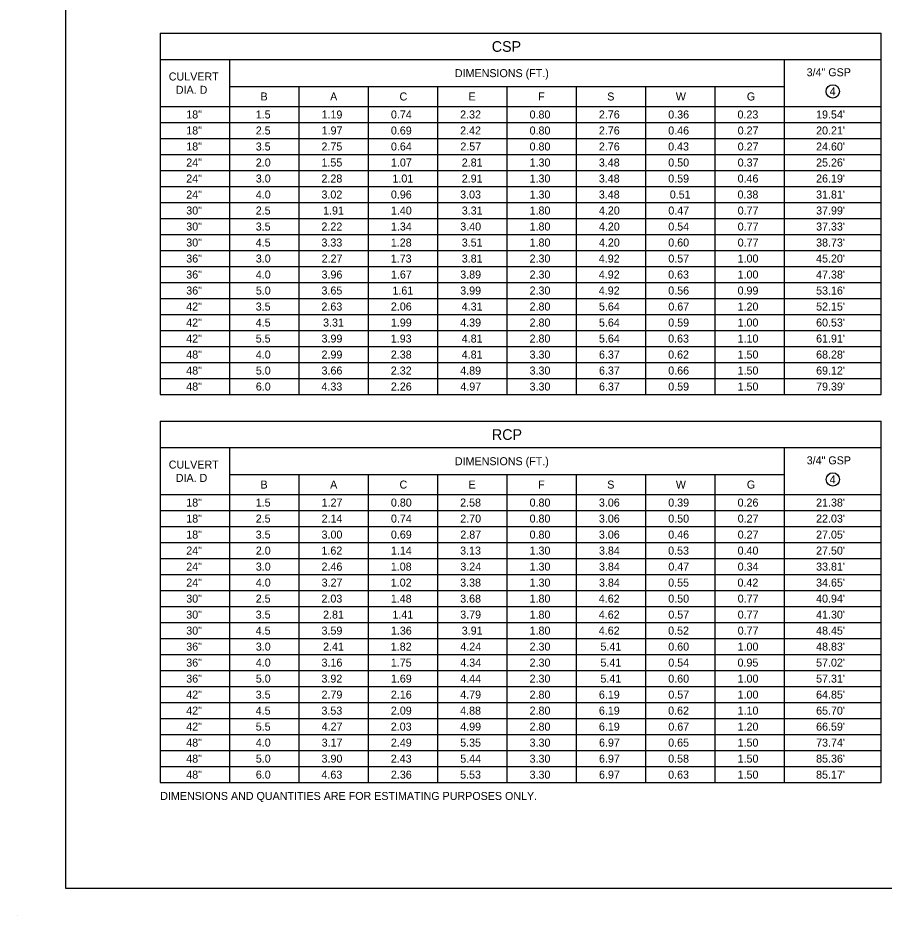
# Model space of a CAD drawing. Extents: x 49991.4 to 50021, y 49987.6 to 50011.4.
# Drawn here: x 49999.02 to 50005.52, y 49987.6 to 49994.33 of the extents above; entities that cross this region are included whole.
import ezdxf

# ---------------------------------------------------------------- set-up
doc = ezdxf.new("R2010")
doc.units = 0
for name, color, linetype in [('Level 1', 7, 'Continuous'), ('Level 2', 7, 'Continuous'), ('Level 3', 7, 'Continuous')]:
    doc.layers.add(name, color=color, linetype=linetype)

msp = doc.modelspace()

# ---------------------------------------------------------------- linework, layer by layer
at = {"layer": 'Level 1'}
msp.add_line((49999.0245, 49987.5988), (49999.0245, 49987.5988), dxfattribs=at)
msp.add_lwpolyline([(49999.3835, 49998.9992), (50016.7501, 49998.9992), (50016.7501, 49987.7988), (49999.3835, 49987.7988)], close=True, dxfattribs=at)
at = {"layer": 'Level 2'}
for p, q in [((50000.0916, 49994.2119), (50005.4993, 49994.2119)), ((50000.0916, 49994.2119), (50000.0916, 49991.5019)), ((50005.4993, 49991.5019), (50005.4993, 49994.2119)), ((50005.4993, 49994.0119), (50000.0916, 49994.0119)), ((50000.6116, 49994.0119), (50000.6116, 49991.5019)), ((50004.7716, 49994.0119), (50004.7716, 49991.5019)), ((50000.6116, 49993.8119), (50004.7716, 49993.8119)), ((50001.1316, 49993.8119), (50001.1316, 49991.5019)), ((50001.6516, 49993.8119), (50001.6516, 49991.5019)), ((50002.1716, 49993.8119), (50002.1716, 49991.5019)), ((50002.6916, 49993.8119), (50002.6916, 49991.5019)), ((50003.2116, 49993.8119), (50003.2116, 49991.5019)), ((50003.7316, 49993.8119), (50003.7316, 49991.5019)), ((50004.2516, 49993.8119), (50004.2516, 49991.5019)), ((50000.0916, 49993.6619), (50005.4993, 49993.6619)), ((50000.0916, 49993.5419), (50005.4993, 49993.5419)), ((50000.0916, 49993.4219), (50005.4993, 49993.4219)), ((50000.0916, 49993.3019), (50005.4993, 49993.3019)), ((50000.0916, 49993.1819), (50005.4993, 49993.1819)), ((50000.0916, 49993.0619), (50005.4993, 49993.0619)), ((50000.0916, 49992.9419), (50005.4993, 49992.9419)), ((50000.0916, 49992.8219), (50005.4993, 49992.8219)), ((50000.0916, 49992.7019), (50005.4993, 49992.7019)), ((50000.0916, 49992.5819), (50005.4993, 49992.5819)), ((50000.0916, 49992.4619), (50005.4993, 49992.4619)), ((50000.0916, 49992.3419), (50005.4993, 49992.3419)), ((50000.0916, 49992.2219), (50005.4993, 49992.2219)), ((50000.0916, 49992.1019), (50005.4993, 49992.1019)), ((50000.0916, 49991.9819), (50005.4993, 49991.9819)), ((50000.0916, 49991.8619), (50005.4993, 49991.8619)), ((50000.0916, 49991.7419), (50005.4993, 49991.7419)), ((50000.0916, 49991.6219), (50005.4993, 49991.6219)), ((50000.0916, 49991.5019), (50005.4993, 49991.5019)), ((50000.0916, 49991.3019), (50005.4993, 49991.3019)), ((50000.0916, 49991.3019), (50000.0916, 49988.5919)), ((50005.4993, 49988.5919), (50005.4993, 49991.3019)), ((50005.4993, 49991.1019), (50000.0916, 49991.1019)), ((50000.6116, 49991.1019), (50000.6116, 49988.5919)), ((50004.7716, 49991.1019), (50004.7716, 49988.5919)), ((50000.6116, 49990.9019), (50004.7716, 49990.9019)), ((50001.1316, 49990.9019), (50001.1316, 49988.5919)), ((50001.6516, 49990.9019), (50001.6516, 49988.5919)), ((50002.1716, 49990.9019), (50002.1716, 49988.5919)), ((50002.6916, 49990.9019), (50002.6916, 49988.5919)), ((50003.2116, 49990.9019), (50003.2116, 49988.5919)), ((50003.7316, 49990.9019), (50003.7316, 49988.5919)), ((50004.2516, 49990.9019), (50004.2516, 49988.5919)), ((50000.0916, 49990.7519), (50005.4993, 49990.7519)), ((50000.0916, 49990.6319), (50005.4993, 49990.6319)), ((50000.0916, 49990.5119), (50005.4993, 49990.5119)), ((50000.0916, 49990.3919), (50005.4993, 49990.3919)), ((50000.0916, 49990.2719), (50005.4993, 49990.2719)), ((50000.0916, 49990.1519), (50005.4993, 49990.1519)), ((50000.0916, 49990.0319), (50005.4993, 49990.0319)), ((50000.0916, 49989.9119), (50005.4993, 49989.9119)), ((50000.0916, 49989.7919), (50005.4993, 49989.7919)), ((50000.0916, 49989.6719), (50005.4993, 49989.6719)), ((50000.0916, 49989.5519), (50005.4993, 49989.5519)), ((50000.0916, 49989.4319), (50005.4993, 49989.4319)), ((50000.0916, 49989.3119), (50005.4993, 49989.3119)), ((50000.0916, 49989.1919), (50005.4993, 49989.1919)), ((50000.0916, 49989.0719), (50005.4993, 49989.0719)), ((50000.0916, 49988.9519), (50005.4993, 49988.9519)), ((50000.0916, 49988.8319), (50005.4993, 49988.8319)), ((50000.0916, 49988.7119), (50005.4993, 49988.7119)), ((50000.0916, 49988.5919), (50005.4993, 49988.5919))]:
    msp.add_line(p, q, dxfattribs=at)
at = {"layer": 'Level 3'}
for centre in [(50005.1354, 49993.7752), (50005.1355, 49990.8652)]:
    msp.add_circle(centre, 0.05, dxfattribs=at)

# ---------------------------------------------------------------- texts
at = {"layer": 'Level 2'}
for s, height, p in [('CSP', 0.08, (50002.5778, 49994.0718)), ('CULVERT', 0.06, (50000.1558, 49993.8569)), ('DIMENSIONS (FT.)', 0.06, (50002.3014, 49993.8819)), ('3/4" GSP', 0.06, (50004.9392, 49993.8885)), ('DIA. D', 0.06, (50000.2087, 49993.7569)), ('B', 0.06, (50000.8439, 49993.7069)), ('A', 0.06, (50001.3658, 49993.7069)), ('C', 0.06, (50001.8861, 49993.7069)), ('E', 0.06, (50002.4036, 49993.7069)), ('F', 0.06, (50002.9254, 49993.7069)), ('S', 0.06, (50003.4438, 49993.7069)), ('W', 0.06, (50003.9583, 49993.7069)), ('G', 0.06, (50004.4909, 49993.7069)), ('4', 0.06, (50005.1115, 49993.7452)), ('18"', 0.06, (50000.2867, 49993.5719)), ('1.5', 0.06, (50000.8079, 49993.5719)), ('1.19', 0.06, (50001.3014, 49993.5719)), ('0.74', 0.06, (50001.8219, 49993.5719)), ('2.32', 0.06, (50002.3407, 49993.5719)), ('0.80', 0.06, (50002.8615, 49993.5719)), ('2.76', 0.06, (50003.3814, 49993.5719)), ('0.36', 0.06, (50003.9014, 49993.5719)), ('0.23', 0.06, (50004.4207, 49993.5719)), ("19.54'", 0.06, (50005.0102, 49993.5719)), ('18"', 0.06, (50000.2867, 49993.4519)), ('2.5', 0.06, (50000.8079, 49993.4519)), ('1.97', 0.06, (50001.3021, 49993.4519)), ('0.69', 0.06, (50001.8214, 49993.4519)), ('2.42', 0.06, (50002.3407, 49993.4519)), ('0.80', 0.06, (50002.8615, 49993.4519)), ('2.76', 0.06, (50003.3814, 49993.4519)), ('0.46', 0.06, (50003.9014, 49993.4519)), ('0.27', 0.06, (50004.4221, 49993.4519)), ("20.21'", 0.06, (50005.0102, 49993.4519)), ('18"', 0.06, (50000.2867, 49993.3319)), ('3.5', 0.06, (50000.8079, 49993.3319)), ('2.75', 0.06, (50001.301, 49993.3319)), ('0.64', 0.06, (50001.8219, 49993.3319)), ('2.57', 0.06, (50002.3421, 49993.3319)), ('0.80', 0.06, (50002.8615, 49993.3319)), ('2.76', 0.06, (50003.3814, 49993.3319)), ('0.43', 0.06, (50003.9007, 49993.3319)), ('0.27', 0.06, (50004.4221, 49993.3319)), ("24.60'", 0.06, (50005.0102, 49993.3319)), ('24"', 0.06, (50000.2867, 49993.2119)), ('2.0', 0.06, (50000.8085, 49993.2119)), ('1.55', 0.06, (50001.301, 49993.2119)), ('1.07', 0.06, (50001.8221, 49993.2119)), ('2.81', 0.06, (50002.3529, 49993.2119)), ('1.30', 0.06, (50002.8615, 49993.2119)), ('3.48', 0.06, (50003.3809, 49993.2119)), ('0.50', 0.06, (50003.9015, 49993.2119)), ('0.37', 0.06, (50004.4221, 49993.2119)), ("25.26'", 0.06, (50005.0102, 49993.2119)), ('24"', 0.06, (50000.2867, 49993.0919)), ('3.0', 0.06, (50000.8085, 49993.0919)), ('2.28', 0.06, (50001.3009, 49993.0919)), ('1.01', 0.06, (50001.8329, 49993.0919)), ('2.91', 0.06, (50002.3529, 49993.0919)), ('1.30', 0.06, (50002.8615, 49993.0919)), ('3.48', 0.06, (50003.3809, 49993.0919)), ('0.59', 0.06, (50003.9014, 49993.0919)), ('0.46', 0.06, (50004.4214, 49993.0919)), ("26.19'", 0.06, (50005.0102, 49993.0919)), ('24"', 0.06, (50000.2867, 49992.9719)), ('4.0', 0.06, (50000.8085, 49992.9719)), ('3.02', 0.06, (50001.3007, 49992.9719)), ('0.96', 0.06, (50001.8214, 49992.9719)), ('3.03', 0.06, (50002.3407, 49992.9719)), ('1.30', 0.06, (50002.8615, 49992.9719)), ('3.48', 0.06, (50003.3809, 49992.9719)), ('0.51', 0.06, (50003.9129, 49992.9719)), ('0.38', 0.06, (50004.4209, 49992.9719)), ("31.81'", 0.06, (50005.0102, 49992.9719)), ('30"', 0.06, (50000.2867, 49992.8519)), ('2.5', 0.06, (50000.8079, 49992.8519)), ('1.91', 0.06, (50001.3129, 49992.8519)), ('1.40', 0.06, (50001.8215, 49992.8519)), ('3.31', 0.06, (50002.3529, 49992.8519)), ('1.80', 0.06, (50002.8615, 49992.8519)), ('4.20', 0.06, (50003.3815, 49992.8519)), ('0.47', 0.06, (50003.9021, 49992.8519)), ('0.77', 0.06, (50004.4221, 49992.8519)), ("37.99'", 0.06, (50005.0102, 49992.8519)), ('30"', 0.06, (50000.2867, 49992.7319)), ('3.5', 0.06, (50000.8079, 49992.7319)), ('2.22', 0.06, (50001.3007, 49992.7319)), ('1.34', 0.06, (50001.8219, 49992.7319)), ('3.40', 0.06, (50002.3415, 49992.7319)), ('1.80', 0.06, (50002.8615, 49992.7319)), ('4.20', 0.06, (50003.3815, 49992.7319)), ('0.54', 0.06, (50003.9019, 49992.7319)), ('0.77', 0.06, (50004.4221, 49992.7319)), ("37.33'", 0.06, (50005.0102, 49992.7319)), ('30"', 0.06, (50000.2867, 49992.6119)), ('4.5', 0.06, (50000.8079, 49992.6119)), ('3.33', 0.06, (50001.3007, 49992.6119)), ('1.28', 0.06, (50001.8209, 49992.6119)), ('3.51', 0.06, (50002.3529, 49992.6119)), ('1.80', 0.06, (50002.8615, 49992.6119)), ('4.20', 0.06, (50003.3815, 49992.6119)), ('0.60', 0.06, (50003.9015, 49992.6119)), ('0.77', 0.06, (50004.4221, 49992.6119)), ("38.73'", 0.06, (50005.0102, 49992.6119)), ('36"', 0.06, (50000.2867, 49992.4919)), ('3.0', 0.06, (50000.8085, 49992.4919)), ('2.27', 0.06, (50001.3021, 49992.4919)), ('1.73', 0.06, (50001.8207, 49992.4919)), ('3.81', 0.06, (50002.3529, 49992.4919)), ('2.30', 0.06, (50002.8615, 49992.4919)), ('4.92', 0.06, (50003.3807, 49992.4919)), ('0.57', 0.06, (50003.9021, 49992.4919)), ('1.00', 0.06, (50004.4215, 49992.4919)), ("45.20'", 0.06, (50005.0102, 49992.4919)), ('36"', 0.06, (50000.2867, 49992.3719)), ('4.0', 0.06, (50000.8085, 49992.3719)), ('3.96', 0.06, (50001.3014, 49992.3719)), ('1.67', 0.06, (50001.8221, 49992.3719)), ('3.89', 0.06, (50002.3414, 49992.3719)), ('2.30', 0.06, (50002.8615, 49992.3719)), ('4.92', 0.06, (50003.3807, 49992.3719)), ('0.63', 0.06, (50003.9007, 49992.3719)), ('1.00', 0.06, (50004.4215, 49992.3719)), ("47.38'", 0.06, (50005.0102, 49992.3719)), ('36"', 0.06, (50000.2867, 49992.2519)), ('5.0', 0.06, (50000.8085, 49992.2519)), ('3.65', 0.06, (50001.301, 49992.2519)), ('1.61', 0.06, (50001.8329, 49992.2519)), ('3.99', 0.06, (50002.3414, 49992.2519)), ('2.30', 0.06, (50002.8615, 49992.2519)), ('4.92', 0.06, (50003.3807, 49992.2519)), ('0.56', 0.06, (50003.9014, 49992.2519)), ('0.99', 0.06, (50004.4214, 49992.2519)), ("53.16'", 0.06, (50005.0102, 49992.2519)), ('42"', 0.06, (50000.2867, 49992.1319)), ('3.5', 0.06, (50000.8079, 49992.1319)), ('2.63', 0.06, (50001.3007, 49992.1319)), ('2.06', 0.06, (50001.8214, 49992.1319)), ('4.31', 0.06, (50002.3529, 49992.1319)), ('2.80', 0.06, (50002.8615, 49992.1319)), ('5.64', 0.06, (50003.3819, 49992.1319)), ('0.67', 0.06, (50003.9021, 49992.1319)), ('1.20', 0.06, (50004.4215, 49992.1319)), ("52.15'", 0.06, (50005.0102, 49992.1319)), ('42"', 0.06, (50000.2867, 49992.0119)), ('4.5', 0.06, (50000.8079, 49992.0119)), ('3.31', 0.06, (50001.3129, 49992.0119)), ('1.99', 0.06, (50001.8214, 49992.0119)), ('4.39', 0.06, (50002.3414, 49992.0119)), ('2.80', 0.06, (50002.8615, 49992.0119)), ('5.64', 0.06, (50003.3819, 49992.0119)), ('0.59', 0.06, (50003.9014, 49992.0119)), ('1.00', 0.06, (50004.4215, 49992.0119)), ("60.53'", 0.06, (50005.0102, 49992.0119)), ('42"', 0.06, (50000.2867, 49991.8919)), ('5.5', 0.06, (50000.8079, 49991.8919)), ('3.99', 0.06, (50001.3014, 49991.8919)), ('1.93', 0.06, (50001.8207, 49991.8919)), ('4.81', 0.06, (50002.3529, 49991.8919)), ('2.80', 0.06, (50002.8615, 49991.8919)), ('5.64', 0.06, (50003.3819, 49991.8919)), ('0.63', 0.06, (50003.9007, 49991.8919)), ('1.10', 0.06, (50004.4215, 49991.8919)), ("61.91'", 0.06, (50005.0102, 49991.8919)), ('48"', 0.06, (50000.2867, 49991.7719)), ('4.0', 0.06, (50000.8085, 49991.7719)), ('2.99', 0.06, (50001.3014, 49991.7719)), ('2.38', 0.06, (50001.8209, 49991.7719)), ('4.81', 0.06, (50002.3529, 49991.7719)), ('3.30', 0.06, (50002.8615, 49991.7719)), ('6.37', 0.06, (50003.3821, 49991.7719)), ('0.62', 0.06, (50003.9007, 49991.7719)), ('1.50', 0.06, (50004.4215, 49991.7719)), ("68.28'", 0.06, (50005.0102, 49991.7719)), ('48"', 0.06, (50000.2867, 49991.6519)), ('5.0', 0.06, (50000.8085, 49991.6519)), ('3.66', 0.06, (50001.3014, 49991.6519)), ('2.32', 0.06, (50001.8207, 49991.6519)), ('4.89', 0.06, (50002.3414, 49991.6519)), ('3.30', 0.06, (50002.8615, 49991.6519)), ('6.37', 0.06, (50003.3821, 49991.6519)), ('0.66', 0.06, (50003.9014, 49991.6519)), ('1.50', 0.06, (50004.4215, 49991.6519)), ("69.12'", 0.06, (50005.0102, 49991.6519)), ('48"', 0.06, (50000.2867, 49991.5319)), ('6.0', 0.06, (50000.8085, 49991.5319)), ('4.33', 0.06, (50001.3007, 49991.5319)), ('2.26', 0.06, (50001.8214, 49991.5319)), ('4.97', 0.06, (50002.3421, 49991.5319)), ('3.30', 0.06, (50002.8615, 49991.5319)), ('6.37', 0.06, (50003.3821, 49991.5319)), ('0.59', 0.06, (50003.9014, 49991.5319)), ('1.50', 0.06, (50004.4215, 49991.5319)), ("79.39'", 0.06, (50005.0102, 49991.5319)), ('RCP', 0.08, (50002.5789, 49991.1618)), ('CULVERT', 0.06, (50000.1556, 49990.9469)), ('DIMENSIONS (FT.)', 0.06, (50002.3014, 49990.9719)), ('3/4" GSP', 0.06, (50004.9398, 49990.9785)), ('DIA. D', 0.06, (50000.2085, 49990.8469)), ('4', 0.06, (50005.1115, 49990.8352)), ('B', 0.06, (50000.8439, 49990.7969)), ('A', 0.06, (50001.3658, 49990.7969)), ('C', 0.06, (50001.8861, 49990.7969)), ('E', 0.06, (50002.4036, 49990.7969)), ('F', 0.06, (50002.9254, 49990.7969)), ('S', 0.06, (50003.4438, 49990.7969)), ('W', 0.06, (50003.9583, 49990.7969)), ('G', 0.06, (50004.4909, 49990.7969)), ('18"', 0.06, (50000.2867, 49990.6619)), ('1.5', 0.06, (50000.8079, 49990.6619)), ('1.27', 0.06, (50001.3021, 49990.6619)), ('0.80', 0.06, (50001.8215, 49990.6619)), ('2.58', 0.06, (50002.3409, 49990.6619)), ('0.80', 0.06, (50002.8615, 49990.6619)), ('3.06', 0.06, (50003.3814, 49990.6619)), ('0.39', 0.06, (50003.9014, 49990.6619)), ('0.26', 0.06, (50004.4214, 49990.6619)), ("21.38'", 0.06, (50005.0102, 49990.6619)), ('18"', 0.06, (50000.2867, 49990.5419)), ('2.5', 0.06, (50000.8079, 49990.5419)), ('2.14', 0.06, (50001.3019, 49990.5419)), ('0.74', 0.06, (50001.8219, 49990.5419)), ('2.70', 0.06, (50002.3415, 49990.5419)), ('0.80', 0.06, (50002.8615, 49990.5419)), ('3.06', 0.06, (50003.3814, 49990.5419)), ('0.50', 0.06, (50003.9015, 49990.5419)), ('0.27', 0.06, (50004.4221, 49990.5419)), ("22.03'", 0.06, (50005.0102, 49990.5419)), ('18"', 0.06, (50000.2867, 49990.4219)), ('3.5', 0.06, (50000.8079, 49990.4219)), ('3.00', 0.06, (50001.3015, 49990.4219)), ('0.69', 0.06, (50001.8214, 49990.4219)), ('2.87', 0.06, (50002.3421, 49990.4219)), ('0.80', 0.06, (50002.8615, 49990.4219)), ('3.06', 0.06, (50003.3814, 49990.4219)), ('0.46', 0.06, (50003.9014, 49990.4219)), ('0.27', 0.06, (50004.4221, 49990.4219)), ("27.05'", 0.06, (50005.0102, 49990.4219)), ('24"', 0.06, (50000.2867, 49990.3019)), ('2.0', 0.06, (50000.8085, 49990.3019)), ('1.62', 0.06, (50001.3007, 49990.3019)), ('1.14', 0.06, (50001.8219, 49990.3019)), ('3.13', 0.06, (50002.3407, 49990.3019)), ('1.30', 0.06, (50002.8615, 49990.3019)), ('3.84', 0.06, (50003.3819, 49990.3019)), ('0.53', 0.06, (50003.9007, 49990.3019)), ('0.40', 0.06, (50004.4215, 49990.3019)), ("27.50'", 0.06, (50005.0102, 49990.3019)), ('24"', 0.06, (50000.2867, 49990.1819)), ('3.0', 0.06, (50000.8085, 49990.1819)), ('2.46', 0.06, (50001.3014, 49990.1819)), ('1.08', 0.06, (50001.8209, 49990.1819)), ('3.24', 0.06, (50002.3419, 49990.1819)), ('1.30', 0.06, (50002.8615, 49990.1819)), ('3.84', 0.06, (50003.3819, 49990.1819)), ('0.47', 0.06, (50003.9021, 49990.1819)), ('0.34', 0.06, (50004.4219, 49990.1819)), ("33.81'", 0.06, (50005.0102, 49990.1819)), ('24"', 0.06, (50000.2867, 49990.0619)), ('4.0', 0.06, (50000.8085, 49990.0619)), ('3.27', 0.06, (50001.3021, 49990.0619)), ('1.02', 0.06, (50001.8207, 49990.0619)), ('3.38', 0.06, (50002.3409, 49990.0619)), ('1.30', 0.06, (50002.8615, 49990.0619)), ('3.84', 0.06, (50003.3819, 49990.0619)), ('0.55', 0.06, (50003.901, 49990.0619)), ('0.42', 0.06, (50004.4207, 49990.0619)), ("34.65'", 0.06, (50005.0102, 49990.0619)), ('30"', 0.06, (50000.2867, 49989.9419)), ('2.5', 0.06, (50000.8079, 49989.9419)), ('2.03', 0.06, (50001.3007, 49989.9419)), ('1.48', 0.06, (50001.8209, 49989.9419)), ('3.68', 0.06, (50002.3409, 49989.9419)), ('1.80', 0.06, (50002.8615, 49989.9419)), ('4.62', 0.06, (50003.3807, 49989.9419)), ('0.50', 0.06, (50003.9015, 49989.9419)), ('0.77', 0.06, (50004.4221, 49989.9419)), ("40.94'", 0.06, (50005.0102, 49989.9419)), ('30"', 0.06, (50000.2867, 49989.8219)), ('3.5', 0.06, (50000.8079, 49989.8219)), ('2.81', 0.06, (50001.3129, 49989.8219)), ('1.41', 0.06, (50001.8329, 49989.8219)), ('3.79', 0.06, (50002.3414, 49989.8219)), ('1.80', 0.06, (50002.8615, 49989.8219)), ('4.62', 0.06, (50003.3807, 49989.8219)), ('0.57', 0.06, (50003.9021, 49989.8219)), ('0.77', 0.06, (50004.4221, 49989.8219)), ("41.30'", 0.06, (50005.0102, 49989.8219)), ('30"', 0.06, (50000.2867, 49989.7019)), ('4.5', 0.06, (50000.8079, 49989.7019)), ('3.59', 0.06, (50001.3014, 49989.7019)), ('1.36', 0.06, (50001.8214, 49989.7019)), ('3.91', 0.06, (50002.3529, 49989.7019)), ('1.80', 0.06, (50002.8615, 49989.7019)), ('4.62', 0.06, (50003.3807, 49989.7019)), ('0.52', 0.06, (50003.9007, 49989.7019)), ('0.77', 0.06, (50004.4221, 49989.7019)), ("48.45'", 0.06, (50005.0102, 49989.7019)), ('36"', 0.06, (50000.2867, 49989.5819)), ('3.0', 0.06, (50000.8085, 49989.5819)), ('2.41', 0.06, (50001.3129, 49989.5819)), ('1.82', 0.06, (50001.8207, 49989.5819)), ('4.24', 0.06, (50002.3419, 49989.5819)), ('2.30', 0.06, (50002.8615, 49989.5819)), ('5.41', 0.06, (50003.3929, 49989.5819)), ('0.60', 0.06, (50003.9015, 49989.5819)), ('1.00', 0.06, (50004.4215, 49989.5819)), ("48.83'", 0.06, (50005.0102, 49989.5819)), ('36"', 0.06, (50000.2867, 49989.4619)), ('4.0', 0.06, (50000.8085, 49989.4619)), ('3.16', 0.06, (50001.3014, 49989.4619)), ('1.75', 0.06, (50001.821, 49989.4619)), ('4.34', 0.06, (50002.3419, 49989.4619)), ('2.30', 0.06, (50002.8615, 49989.4619)), ('5.41', 0.06, (50003.3929, 49989.4619)), ('0.54', 0.06, (50003.9019, 49989.4619)), ('0.95', 0.06, (50004.421, 49989.4619)), ("57.02'", 0.06, (50005.0102, 49989.4619)), ('36"', 0.06, (50000.2867, 49989.3419)), ('5.0', 0.06, (50000.8085, 49989.3419)), ('3.92', 0.06, (50001.3007, 49989.3419)), ('1.69', 0.06, (50001.8214, 49989.3419)), ('4.44', 0.06, (50002.3419, 49989.3419)), ('2.30', 0.06, (50002.8615, 49989.3419)), ('5.41', 0.06, (50003.3929, 49989.3419)), ('0.60', 0.06, (50003.9015, 49989.3419)), ('1.00', 0.06, (50004.4215, 49989.3419)), ("57.31'", 0.06, (50005.0102, 49989.3419)), ('42"', 0.06, (50000.2867, 49989.2219)), ('3.5', 0.06, (50000.8079, 49989.2219)), ('2.79', 0.06, (50001.3014, 49989.2219)), ('2.16', 0.06, (50001.8214, 49989.2219)), ('4.79', 0.06, (50002.3414, 49989.2219)), ('2.80', 0.06, (50002.8615, 49989.2219)), ('6.19', 0.06, (50003.3814, 49989.2219)), ('0.57', 0.06, (50003.9021, 49989.2219)), ('1.00', 0.06, (50004.4215, 49989.2219)), ("64.85'", 0.06, (50005.0102, 49989.2219)), ('42"', 0.06, (50000.2867, 49989.1019)), ('4.5', 0.06, (50000.8079, 49989.1019)), ('3.53', 0.06, (50001.3007, 49989.1019)), ('2.09', 0.06, (50001.8214, 49989.1019)), ('4.88', 0.06, (50002.3409, 49989.1019)), ('2.80', 0.06, (50002.8615, 49989.1019)), ('6.19', 0.06, (50003.3814, 49989.1019)), ('0.62', 0.06, (50003.9007, 49989.1019)), ('1.10', 0.06, (50004.4215, 49989.1019)), ("65.70'", 0.06, (50005.0102, 49989.1019)), ('42"', 0.06, (50000.2867, 49988.9819)), ('5.5', 0.06, (50000.8079, 49988.9819)), ('4.27', 0.06, (50001.3021, 49988.9819)), ('2.03', 0.06, (50001.8207, 49988.9819)), ('4.99', 0.06, (50002.3414, 49988.9819)), ('2.80', 0.06, (50002.8615, 49988.9819)), ('6.19', 0.06, (50003.3814, 49988.9819)), ('0.67', 0.06, (50003.9021, 49988.9819)), ('1.20', 0.06, (50004.4215, 49988.9819)), ("66.59'", 0.06, (50005.0102, 49988.9819)), ('48"', 0.06, (50000.2867, 49988.8619)), ('4.0', 0.06, (50000.8085, 49988.8619)), ('3.17', 0.06, (50001.3021, 49988.8619)), ('2.49', 0.06, (50001.8214, 49988.8619)), ('5.35', 0.06, (50002.341, 49988.8619)), ('3.30', 0.06, (50002.8615, 49988.8619)), ('6.97', 0.06, (50003.3821, 49988.8619)), ('0.65', 0.06, (50003.901, 49988.8619)), ('1.50', 0.06, (50004.4215, 49988.8619)), ("73.74'", 0.06, (50005.0102, 49988.8619)), ('48"', 0.06, (50000.2867, 49988.7419)), ('5.0', 0.06, (50000.8085, 49988.7419)), ('3.90', 0.06, (50001.3015, 49988.7419)), ('2.43', 0.06, (50001.8207, 49988.7419)), ('5.44', 0.06, (50002.3419, 49988.7419)), ('3.30', 0.06, (50002.8615, 49988.7419)), ('6.97', 0.06, (50003.3821, 49988.7419)), ('0.58', 0.06, (50003.9009, 49988.7419)), ('1.50', 0.06, (50004.4215, 49988.7419)), ("85.36'", 0.06, (50005.0102, 49988.7419)), ('48"', 0.06, (50000.2867, 49988.6219)), ('6.0', 0.06, (50000.8085, 49988.6219)), ('4.63', 0.06, (50001.3007, 49988.6219)), ('2.36', 0.06, (50001.8214, 49988.6219)), ('5.53', 0.06, (50002.3407, 49988.6219)), ('3.30', 0.06, (50002.8615, 49988.6219)), ('6.97', 0.06, (50003.3821, 49988.6219)), ('0.63', 0.06, (50003.9007, 49988.6219)), ('1.50', 0.06, (50004.4215, 49988.6219)), ("85.17'", 0.06, (50005.0102, 49988.6219)), ('DIMENSIONS AND QUANTITIES ARE FOR ESTIMATING PURPOSES ONLY.', 0.06, (50000.0916, 49988.4619))]:
    msp.add_text(s, height=height, dxfattribs=at).set_placement(p)

doc.saveas('drawing.dxf')
